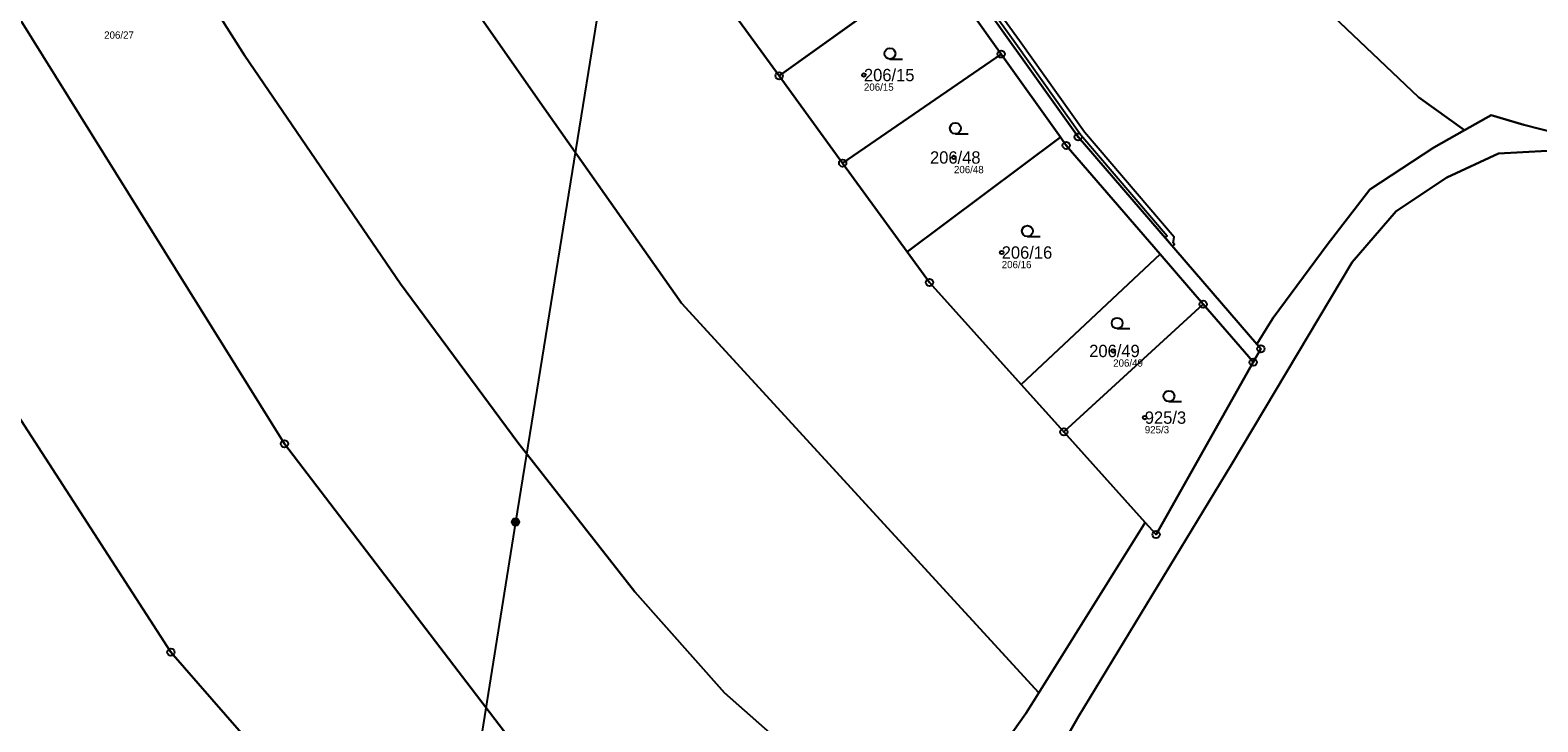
# Model space of a CAD drawing. Extents: x -734504 to -730695, y -1027923 to -1024502.
# Drawn here: x -732210.1 to -732002.6, y -1027777 to -1027681.8 of the extents above; entities that cross this region are included whole.
import ezdxf

# ---------------------------------------------------------------- set-up
doc = ezdxf.new("R2010")
doc.units = 0
for name, color, linetype in [('Definiční body', 7, 'Continuous'), ('Hranice parcel', 7, 'Continuous'), ('Parcelní čísla', 7, 'Continuous'), ('Polygon ku', 7, 'Continuous'), ('Polygon parcely', 7, 'Continuous'), ('Poz předměty', 7, 'Continuous'), ('Věcná břemena k části', 7, 'Continuous'), ('Značky bodu BP', 7, 'Continuous'), ('Značky kultur', 7, 'Continuous')]:
    doc.layers.add(name, color=color, linetype=linetype)

msp = doc.modelspace()

# ---------------------------------------------------------------- linework, layer by layer
at = {"layer": 'Definiční body'}
for centre in [(-732095.33, -1027688.02), (-732082.94, -1027699.36), (-732076.37, -1027712.43), (-732061.03, -1027725.97), (-732056.68, -1027735.14)]:
    msp.add_circle(centre, 0.25, dxfattribs=at)
at = {"layer": 'Hranice parcel'}
for p, q in [((-732106.99, -1027688.13), (-732085.36, -1027672.64)), ((-732085.36, -1027672.64), (-732076.45, -1027685.13)), ((-732116.66, -1027674.85), (-732106.99, -1027688.13)), ((-732098.26, -1027700.13), (-732076.45, -1027685.13)), ((-732076.45, -1027685.13), (-732068.29, -1027696.58)), ((-732106.99, -1027688.13), (-732098.26, -1027700.13)), ((-732068.29, -1027696.58), (-732089.36, -1027712.35)), ((-732098.26, -1027700.13), (-732089.36, -1027712.35)), ((-732073.68, -1027730.59), (-732054.58, -1027712.66)), ((-732054.58, -1027712.66), (-732048.63, -1027719.55)), ((-732048.63, -1027719.55), (-732067.81, -1027737.11)), ((-732073.68, -1027730.59), (-732067.81, -1027737.11)), ((-732067.81, -1027737.11), (-732056.62, -1027749.56)), ((-732056.62, -1027749.56), (-732071.28, -1027772.99))]:
    msp.add_line(p, q, dxfattribs=at)
for points in [[(-732041.27, -1027725.02), (-732065.86, -1027696.54), (-732083.2, -1027672.23), (-732101.44, -1027646.5), (-732136.73, -1027593.25), (-732173.87, -1027532.76)], [(-732134.58, -1027544.7), (-732106.08, -1027589.26), (-732098.4, -1027599.88), (-732076.9, -1027627.81), (-732060.22, -1027648.7), (-732046.69, -1027663.23), (-732031.64, -1027679.09), (-732019.02, -1027691.08), (-732012.67, -1027695.59)], [(-732071.28, -1027772.99), (-732120.43, -1027719.4), (-732139.34, -1027692.57), (-732159.49, -1027663.78), (-732171.87, -1027645.58), (-732202.11, -1027596.66), (-732221.09, -1027565.19), (-732228.56, -1027551.79)], [(-732251.88, -1027569.09), (-732238.86, -1027591.46), (-732224.53, -1027616.37), (-732203.76, -1027648.81), (-732180.55, -1027685.37), (-732159.11, -1027716.73), (-732142.97, -1027738.56), (-732126.86, -1027759.09), (-732114.52, -1027772.99), (-732087.77, -1027796.61)], [(-732312.09, -1027581.03), (-732260.26, -1027659.86), (-732190.7, -1027767.4), (-732147.15, -1027817.32), (-732116.28, -1027848.45)], [(-732102, -1027821.35), (-732121.92, -1027802.79), (-732142.41, -1027781.48), (-732175.08, -1027738.73), (-732224.9, -1027658.83), (-732274.49, -1027584.25)], [(-732012.67, -1027695.59), (-732009.01, -1027693.52), (-732004.54, -1027694.86), (-731998.06, -1027696.5)], [(-732012.67, -1027695.59), (-732016.89, -1027697.97), (-732025.7, -1027703.76), (-732031.58, -1027711.39), (-732039.02, -1027721.41), (-732039.57, -1027722.3), (-732041.27, -1027725.02)], [(-732068.29, -1027696.58), (-732067.49, -1027697.7), (-732054.58, -1027712.66)], [(-731990.6, -1027701.66), (-731994.83, -1027700.15), (-732001.33, -1027698.46), (-732008.01, -1027698.81), (-732015.13, -1027702.11), (-732022.08, -1027706.74), (-732028.13, -1027713.78)], [(-732089.36, -1027712.35), (-732086.31, -1027716.54), (-732073.68, -1027730.59)], [(-732028.13, -1027713.78), (-732044.76, -1027741.57), (-732065.81, -1027776.27), (-732081.98, -1027804.5), (-732095.33, -1027826.59), (-732113.92, -1027856.91), (-732123.62, -1027871.74), (-732140.29, -1027885.06), (-732153.55, -1027893.39), (-732160.23, -1027900.96)], [(-732041.75, -1027727.53), (-732042.38, -1027726.8), (-732048.63, -1027719.55)], [(-732041.75, -1027727.53), (-732040.7, -1027725.68), (-732041.27, -1027725.02)], [(-732056.62, -1027749.56), (-732055.13, -1027751.21), (-732041.75, -1027727.53)], [(-732087.77, -1027796.61), (-732073.05, -1027775.82), (-732071.28, -1027772.99)]]:
    msp.add_lwpolyline(points, dxfattribs=at)
at = {"layer": 'Polygon ku'}
msp.add_lwpolyline([(-732081.98, -1027804.5), (-732065.81, -1027776.27), (-732044.76, -1027741.57), (-732028.13, -1027713.78), (-732022.08, -1027706.74), (-732015.13, -1027702.11), (-732008.01, -1027698.81), (-732001.33, -1027698.46)], dxfattribs=at)
at = {"layer": 'Polygon parcely'}
for points in [[(-731997.76, -1027575.65), (-732030.06, -1027542.8), (-732050.67, -1027521.91), (-732059.77, -1027511.74), (-732134.58, -1027544.7), (-732106.08, -1027589.26), (-732098.4, -1027599.88), (-732076.9, -1027627.81), (-732060.22, -1027648.7), (-732046.69, -1027663.23), (-732031.64, -1027679.09), (-732019.02, -1027691.08), (-732012.67, -1027695.59), (-732009.01, -1027693.52), (-732004.54, -1027694.86), (-731998.06, -1027696.5)], [(-732159.49, -1027663.78), (-732139.34, -1027692.57), (-732120.43, -1027719.4), (-732071.28, -1027772.99), (-732056.62, -1027749.56), (-732067.81, -1027737.11), (-732073.68, -1027730.59), (-732086.31, -1027716.54), (-732089.36, -1027712.35), (-732098.26, -1027700.13), (-732106.99, -1027688.13), (-732116.66, -1027674.85)], [(-732085.36, -1027672.64), (-732076.45, -1027685.13), (-732068.29, -1027696.58), (-732067.49, -1027697.7), (-732054.58, -1027712.66), (-732048.63, -1027719.55), (-732042.38, -1027726.8), (-732041.75, -1027727.53), (-732040.7, -1027725.68), (-732041.27, -1027725.02), (-732065.86, -1027696.54), (-732083.2, -1027672.23)], [(-732083.2, -1027672.23), (-732065.86, -1027696.54), (-732041.27, -1027725.02), (-732039.57, -1027722.3), (-732039.02, -1027721.41), (-732031.58, -1027711.39), (-732025.7, -1027703.76), (-732016.89, -1027697.97), (-732012.67, -1027695.59), (-732019.02, -1027691.08), (-732031.64, -1027679.09)], [(-731998.06, -1027696.5), (-732004.54, -1027694.86), (-732009.01, -1027693.52), (-732012.67, -1027695.59), (-732016.89, -1027697.97), (-732025.7, -1027703.76), (-732031.58, -1027711.39), (-732039.02, -1027721.41), (-732039.57, -1027722.3), (-732041.27, -1027725.02), (-732040.7, -1027725.68), (-732041.75, -1027727.53), (-732055.13, -1027751.21), (-732056.62, -1027749.56), (-732071.28, -1027772.99), (-732073.05, -1027775.82), (-732087.77, -1027796.61)], [(-732081.98, -1027804.5), (-732065.81, -1027776.27), (-732044.76, -1027741.57), (-732028.13, -1027713.78), (-732022.08, -1027706.74), (-732015.13, -1027702.11), (-732008.01, -1027698.81), (-732001.33, -1027698.46)]]:
    msp.add_lwpolyline(points, dxfattribs=at)
for points in [[(-732238.86, -1027591.46), (-732224.53, -1027616.37), (-732203.76, -1027648.81), (-732180.55, -1027685.37), (-732159.11, -1027716.73), (-732142.97, -1027738.56), (-732126.86, -1027759.09), (-732114.52, -1027772.99), (-732087.77, -1027796.61), (-732073.05, -1027775.82), (-732071.28, -1027772.99), (-732120.43, -1027719.4), (-732139.34, -1027692.57), (-732159.49, -1027663.78), (-732171.87, -1027645.58), (-732202.11, -1027596.66), (-732221.09, -1027565.19), (-732228.56, -1027551.79), (-732236.28, -1027556.74), (-732251.88, -1027569.09)], [(-732107.88, -1027832.63), (-732102, -1027821.35), (-732121.92, -1027802.79), (-732142.41, -1027781.48), (-732175.08, -1027738.73), (-732224.9, -1027658.83), (-732274.49, -1027584.25), (-732276.56, -1027585.6), (-732291.46, -1027566.59), (-732312.09, -1027581.03), (-732260.26, -1027659.86), (-732190.7, -1027767.4), (-732147.15, -1027817.32), (-732116.28, -1027848.45)], [(-732274.49, -1027584.25), (-732224.9, -1027658.83), (-732175.08, -1027738.73), (-732142.41, -1027781.48), (-732121.92, -1027802.79), (-732102, -1027821.35), (-732099.45, -1027816.44), (-732091.08, -1027801.29), (-732087.77, -1027796.61), (-732114.52, -1027772.99), (-732126.86, -1027759.09), (-732142.97, -1027738.56), (-732159.11, -1027716.73), (-732180.55, -1027685.37), (-732203.76, -1027648.81), (-732224.53, -1027616.37), (-732238.86, -1027591.46), (-732251.88, -1027569.09), (-732255.31, -1027571.8)], [(-732116.28, -1027848.45), (-732147.15, -1027817.32), (-732190.7, -1027767.4), (-732260.26, -1027659.86), (-732312.09, -1027581.03), (-732335.36, -1027602.6), (-732283.8, -1027673.77), (-732206.59, -1027791.64), (-732163.03, -1027842.69), (-732135.21, -1027873.43), (-732132.61, -1027871.23), (-732125.05, -1027862.35), (-732117.27, -1027850.32)], [(-732106.99, -1027688.13), (-732085.36, -1027672.64), (-732095.14, -1027658.85), (-732116.66, -1027674.85)], [(-732098.26, -1027700.13), (-732076.45, -1027685.13), (-732085.36, -1027672.64), (-732106.99, -1027688.13)], [(-732089.36, -1027712.35), (-732068.29, -1027696.58), (-732076.45, -1027685.13), (-732098.26, -1027700.13)], [(-732073.68, -1027730.59), (-732054.58, -1027712.66), (-732067.49, -1027697.7), (-732068.29, -1027696.58), (-732089.36, -1027712.35), (-732086.31, -1027716.54)], [(-732067.81, -1027737.11), (-732048.63, -1027719.55), (-732054.58, -1027712.66), (-732073.68, -1027730.59)], [(-732041.75, -1027727.53), (-732042.38, -1027726.8), (-732048.63, -1027719.55), (-732067.81, -1027737.11), (-732056.62, -1027749.56), (-732055.13, -1027751.21)]]:
    msp.add_lwpolyline(points, close=True, dxfattribs=at)
at = {"layer": 'Poz předměty'}
for p, q in [((-732121.4, -1027614.07), (-732143.28, -1027749.5)), ((-732143.28, -1027749.5), (-732166.07, -1027892.68))]:
    msp.add_line(p, q, dxfattribs=at)
for radius in [0.5, 0.4, 0.3, 0.2, 0.1]:
    msp.add_circle((-732143.28, -1027749.5), radius, dxfattribs=at)
at = {"layer": 'Věcná břemena k části'}
msp.add_lwpolyline([(-732086.64, -1027666.74), (-732074.41, -1027683.68), (-732065.46, -1027696.26), (-732053.6, -1027710.13), (-732053.86, -1027710.33), (-732052.86, -1027711.58), (-732052.57, -1027711.33), (-732052.78, -1027711.09), (-732052.65, -1027710.31), (-732064.98, -1027695.89), (-732073.92, -1027683.33), (-732086.15, -1027666.4)], dxfattribs=at)
at = {"layer": 'Značky bodu BP'}
for centre, radius in [((-732076.45, -1027685.13), 0.5), ((-732076.45, -1027685.13), 0.0303), ((-732106.99, -1027688.13), 0.5), ((-732106.99, -1027688.13), 0.0303), ((-732065.86, -1027696.54), 0.5), ((-732067.49, -1027697.7), 0.5), ((-732067.49, -1027697.7), 0.0303), ((-732065.86, -1027696.54), 0.0303), ((-732098.26, -1027700.13), 0.5), ((-732098.26, -1027700.13), 0.0303), ((-732086.31, -1027716.54), 0.5), ((-732086.31, -1027716.54), 0.0303), ((-732048.63, -1027719.55), 0.5), ((-732048.63, -1027719.55), 0.0303), ((-732041.75, -1027727.53), 0.5), ((-732040.7, -1027725.68), 0.5), ((-732040.7, -1027725.68), 0.0303), ((-732041.75, -1027727.53), 0.0303), ((-732067.81, -1027737.11), 0.5), ((-732067.81, -1027737.11), 0.0303), ((-732175.08, -1027738.73), 0.5), ((-732175.08, -1027738.73), 0.0303), ((-732055.13, -1027751.21), 0.5), ((-732055.13, -1027751.21), 0.0303), ((-732190.7, -1027767.4), 0.5), ((-732190.7, -1027767.4), 0.0303)]:
    msp.add_circle(centre, radius, dxfattribs=at)
at = {"layer": 'Značky kultur'}
for p, q in [((-732091.76, -1027685.82), (-732090.01, -1027685.82)), ((-732082.75, -1027696.1), (-732081, -1027696.1)), ((-732072.84, -1027710.23), (-732071.09, -1027710.23)), ((-732060.48, -1027722.9), (-732058.73, -1027722.9)), ((-732053.36, -1027732.94), (-732051.61, -1027732.94))]:
    msp.add_line(p, q, dxfattribs=at)
for centre in [(-732091.76, -1027685.07), (-732082.75, -1027695.35), (-732072.84, -1027709.48), (-732060.48, -1027722.15), (-732053.36, -1027732.19)]:
    msp.add_circle(centre, 0.75, dxfattribs=at)

# ---------------------------------------------------------------- texts
at = {"layer": 'Definiční body'}
for s, p in [('206/27', (-732199.89, -1027683.02)), ('206/15', (-732095.33, -1027690.18)), ('206/48', (-732082.94, -1027701.52)), ('206/16', (-732076.37, -1027714.59)), ('206/49', (-732061.03, -1027728.13)), ('925/3', (-732056.68, -1027737.3))]:
    msp.add_text(s, height=1, dxfattribs=at).set_placement(p)
at = {"layer": 'Parcelní čísla'}
for s, p in [('206/15', (-732095.33, -1027688.87)), ('206/48', (-732086.24, -1027700.21)), ('206/16', (-732076.37, -1027713.28)), ('206/49', (-732064.33, -1027726.82)), ('925/3', (-732056.68, -1027735.99))]:
    msp.add_text(s, height=1.7, dxfattribs=at).set_placement(p)

doc.saveas('drawing.dxf')
